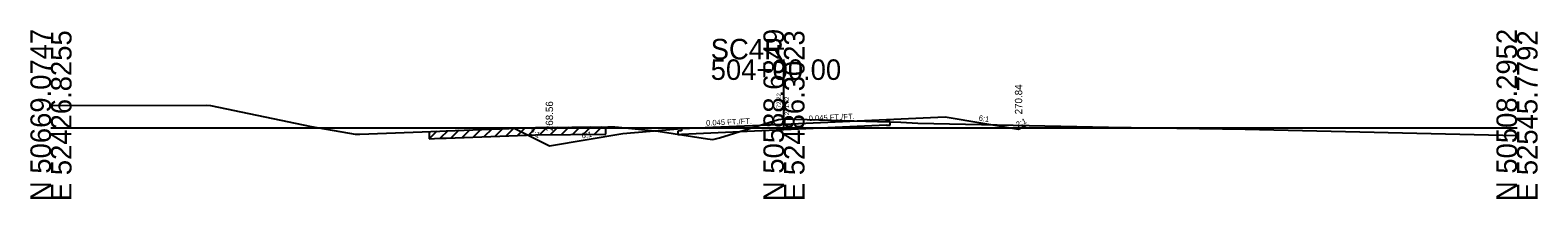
# Model space of a CAD drawing. Extents: x 7498 to 13027, y 90095 to 109625.
# Drawn here: x 8521.2 to 8726.8, y 94095.5 to 94118.5 of the extents above; entities that cross this region are included whole.
import ezdxf

# ---------------------------------------------------------------- set-up
doc = ezdxf.new("R2010")
doc.units = 0
for name, color, linetype in [('Level 10', 7, 'Continuous'), ('Level 11', 7, 'Continuous'), ('Level 12', 7, 'Continuous'), ('Level 32', 7, 'Continuous'), ('Level 33', 7, 'Continuous'), ('Level 59', 7, 'Continuous'), ('Level 6', 7, 'Continuous'), ('Level 60', 7, 'Continuous'), ('Level 61', 7, 'Continuous'), ('Level 63', 7, 'Continuous'), ('Level 7', 7, 'Continuous')]:
    doc.layers.add(name, color=color, linetype=linetype)

msp = doc.modelspace()

# ---------------------------------------------------------------- linework, layer by layer
at = {"layer": 'Level 11'}
for p, q in [((8637.99, 94106.01), (8637.99, 94106.31)), ((8638.49, 94106.03), (8637.99, 94106.01)), ((8637.99, 94105.53), (8638.49, 94105.55)), ((8638.49, 94105.55), (8638.49, 94106.03)), ((8609.99, 94104.75), (8609.49, 94104.72)), ((8609.49, 94104.72), (8609.49, 94104.24)), ((8609.49, 94104.24), (8609.99, 94104.27)), ((8609.99, 94105.05), (8609.99, 94104.75))]:
    msp.add_line(p, q, dxfattribs=at)
at = {"layer": 'Level 12'}
for p, q in [((8637.99, 94105.53), (8623.99, 94104.9)), ((8623.99, 94104.9), (8609.99, 94104.27))]:
    msp.add_line(p, q, dxfattribs=at)
at = {"layer": 'Level 59'}
for p, q in [((8609.99, 94105.05), (8623.99, 94105.68)), ((8623.99, 94105.68), (8637.99, 94106.31))]:
    msp.add_line(p, q, dxfattribs=at)
at = {"layer": 'Level 6'}
for p, q in [((8637.99, 94106.31), (8645.99, 94106.67)), ((8601.99, 94104.38), (8609.99, 94105.05))]:
    msp.add_line(p, q, dxfattribs=at)
at = {"layer": 'Level 60'}
for p, q in [((8523.99, 94108.23), (8545.18, 94108.28)), ((8545.18, 94108.28), (8545.75, 94108.22)), ((8545.75, 94108.22), (8559.49, 94105.35)), ((8615.18, 94103.82), (8623.26, 94106.31)), ((8623.26, 94106.31), (8623.99, 94106.37)), ((8623.99, 94106.37), (8639.92, 94105.95)), ((8639.92, 94105.95), (8642.27, 94105.82)), ((8642.27, 94105.82), (8668.26, 94105.26)), ((8559.49, 94105.35), (8565.47, 94104.31)), ((8565.47, 94104.31), (8566.13, 94104.3)), ((8566.13, 94104.3), (8577.05, 94104.73)), ((8577.05, 94104.73), (8577.89, 94104.76)), ((8577.89, 94104.76), (8590.08, 94105.22)), ((8590.08, 94105.22), (8599.98, 94105.3)), ((8599.98, 94105.3), (8600.91, 94105.32)), ((8600.91, 94105.32), (8601.43, 94105.27)), ((8601.43, 94105.27), (8606.82, 94104.7)), ((8606.82, 94104.7), (8613.54, 94103.68)), ((8613.54, 94103.68), (8614.3, 94103.58)), ((8614.3, 94103.58), (8615.18, 94103.82)), ((8668.26, 94105.26), (8686.92, 94104.96)), ((8686.92, 94104.96), (8723.99, 94104.11))]:
    msp.add_line(p, q, dxfattribs=at)
at = {"layer": 'Level 61'}
for p, q in [((8576.64, 94104.71), (8575.6, 94103.67)), ((8575.6, 94104.67), (8575.6, 94103.67)), ((8575.6, 94103.67), (8577.05, 94103.73)), ((8577.05, 94103.73), (8577.89, 94103.76)), ((8578.14, 94104.77), (8577.1, 94103.73)), ((8577.89, 94103.76), (8590.08, 94104.22)), ((8579.64, 94104.83), (8578.6, 94103.79)), ((8581.14, 94104.88), (8580.1, 94103.84)), ((8582.65, 94104.94), (8581.61, 94103.9)), ((8584.15, 94104.99), (8583.11, 94103.96)), ((8585.65, 94105.05), (8584.61, 94104.01)), ((8587.15, 94105.11), (8586.11, 94104.07)), ((8588.66, 94105.16), (8587.62, 94104.12)), ((8590.16, 94105.22), (8589.12, 94104.18)), ((8590.08, 94104.22), (8599.7, 94104.3)), ((8591.63, 94105.23), (8590.62, 94104.22)), ((8593.13, 94105.24), (8592.12, 94104.24)), ((8594.64, 94105.26), (8593.63, 94104.25)), ((8596.14, 94105.27), (8595.13, 94104.26)), ((8597.64, 94105.28), (8596.63, 94104.28)), ((8599.14, 94105.3), (8598.13, 94104.29)), ((8599.7, 94104.3), (8599.7, 94105.3))]:
    msp.add_line(p, q, dxfattribs=at)
at = {"layer": 'Level 63'}
for p, q in [((8623.99, 94105.16), (8623.99, 94114.51)), ((8523.99, 94105.16), (8623.99, 94105.16)), ((8623.99, 94105.16), (8723.99, 94105.16))]:
    msp.add_line(p, q, dxfattribs=at)
at = {"layer": 'Level 7'}
for p, q in [((8645.99, 94106.67), (8655.99, 94105)), ((8655.99, 94105), (8657, 94105.5)), ((8587.2, 94105.11), (8591.99, 94102.71)), ((8591.99, 94102.71), (8601.99, 94104.38))]:
    msp.add_line(p, q, dxfattribs=at)

# ---------------------------------------------------------------- texts
at = {"layer": 'Level 10'}
msp.add_text('272.22', height=0.6, rotation=90, dxfattribs=at).set_placement((8623.59, 94107.37))
at = {"layer": 'Level 32'}
for s, rotation, p in [('0.045 FT./FT.', 2.5766, (8613.38, 94105.45)), ('0.045 FT./FT.', 2.5766, (8627.38, 94106.08)), ('6:1', 350.5377, (8650.51, 94106.17)), ('2:1', 26.5651, (8655.88, 94105.22)), ('2:1', 333.435, (8589.2, 94104.39)), ('6:1', 9.4623, (8596.43, 94103.71))]:
    msp.add_text(s, height=0.75, rotation=rotation, dxfattribs=at).set_placement(p)
at = {"layer": 'Level 33'}
for s, p in [('270.84', (8656.49, 94107)), ('268.56', (8592.49, 94104.71))]:
    msp.add_text(s, height=1, rotation=90, dxfattribs=at).set_placement(p)
at = {"layer": 'Level 59'}
msp.add_text(' 271.52', height=0.6, rotation=90, dxfattribs=at).set_placement((8624.69, 94106.67))
at = {"layer": 'Level 63'}
for s, p in [('N 50669.0747', (8523.99, 94095.16)), ('E 52426.8255', (8526.79, 94095.16)), ('N 50588.6849', (8623.99, 94095.16)), ('E 52486.3023', (8626.79, 94095.16)), ('N 50508.2952', (8723.99, 94095.16)), ('E 52545.7792', (8726.79, 94095.16))]:
    msp.add_text(s, height=2.8, rotation=90, dxfattribs=at).set_placement(p)
for s, p in [('SC4R', (8613.99, 94114.51)), ('504+00.00', (8613.99, 94111.71))]:
    msp.add_text(s, height=2.8, dxfattribs=at).set_placement(p)

doc.saveas('drawing.dxf')
